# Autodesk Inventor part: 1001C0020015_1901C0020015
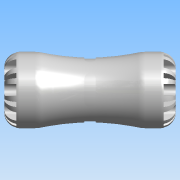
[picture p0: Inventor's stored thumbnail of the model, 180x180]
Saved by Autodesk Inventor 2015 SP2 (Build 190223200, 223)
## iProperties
Created: 2016-12
Part Number: 1001C0020015_1901C0020015
Material: PVC-Piping
Description: PLASSON COPPER PIPE ADAPTOR 20X15 SERIES 1
Document SubType Name: Modeling
Designer: KIM
Mass: 95.2094 g
Surface Area: 200.83 cm^2
Volume: 68.0067 cm^3
Density: 1.4 g/cm^3
Appearance: Smooth - White
ILogicFactory: False
Author: KIM
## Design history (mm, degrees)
derived "1001C.ipt"
feature "Solid1::1001C.ipt"
tag "TaggingFeature1"
body "Solid1"
other parameters: "d1" = 41, "d2" = 45, "d11" = 6.4, "d13" = 6.4, "d14" = 0, "d16" = 360 deg, "d18" = 8 deg, "d19" = 0.4, "d20" = 8 deg, "d21" = 0.4, "d23" = 0, "d25" = 360 deg, "d27" = 16.4, "d28" = 6, "d29" = 6, "d30" = 12.544, "d31" = 0, "d33" = 0, "d37" = 18.4, "d38" = 0.41, "d45" = 18.4, "d46" = 34.85, "d47" = 41, "d50" = 360 deg, "d54" = 0.513, "d60" = 15, "d61" = 25, "d62" = 41, "d63" = 18.4, "d64" = 92, "d65" = 46, "d66" = 1.25, "d67" = 46, "d70" = 6.4, "d72" = 6.4, "d73" = 0, "d75" = 360 deg, "d77" = 8 deg, "d78" = 8 deg, "d79" = 0.4, "d80" = 0.4, "d82" = 0, "d84" = 360 deg, "d87" = 25, "E_" = 41, "H_" = 92, "l_" = 45, "d_1" = 15, "E_1" = 41, "l_1" = 46, "d12" = 25, "d42" = 41, "d52" = 8, "d68" = 41, "d69" = 25, "d71" = 8
